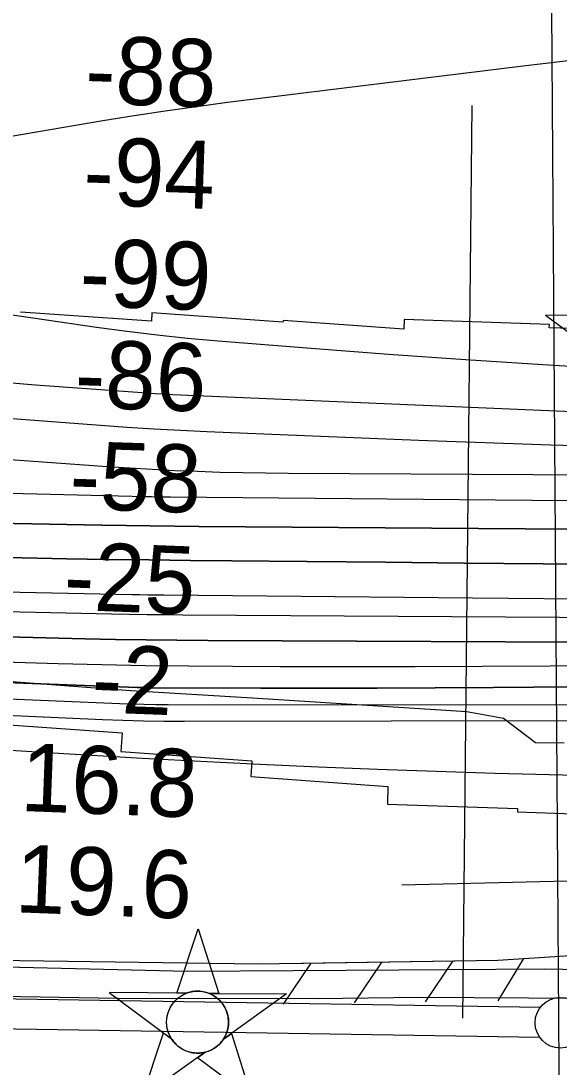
# Model space of a CAD drawing. Extents: x 3508733 to 3546731, y 546897 to 572481.
# Drawn here: x 3533417 to 3533948, y 561954 to 562985 of the extents above; entities that cross this region are included whole.
import ezdxf

# ---------------------------------------------------------------- set-up
doc = ezdxf.new("R2010")
doc.units = 0
for name, color, linetype in [('V-CHAN-NAID', 7, 'Continuous'), ('V-FLOD-BASE', 7, 'Continuous'), ('V-GRID-MAJR', 7, 'Continuous'), ('V-LEVE-TOET', 7, 'Continuous'), ('V-RIVR-EDGE', 7, 'Continuous'), ('V-RIVR-RANG', 7, 'Continuous'), ('V-RRAP-FSHR', 7, 'Continuous'), ('V-RRAP-RVMT', 7, 'Continuous'), ('V-SURV-LINE', 7, 'Continuous'), ('V-TOPO-DPTH', 7, 'Continuous'), ('V-TOPO-MAJR', 7, 'Continuous'), ('V-TOPO-MINR', 7, 'Continuous'), ('V-TOPO-WATR', 7, 'Continuous')]:
    doc.layers.add(name, color=color, linetype=linetype)

msp = doc.modelspace()

# ---------------------------------------------------------------- linework, layer by layer
at = {"layer": 'V-CHAN-NAID'}
msp.add_lwpolyline([(3534011.036, 562694.7280000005), (3533934.545, 562695.2700000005), (3533996.11, 562649.8710000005)], dxfattribs=at)
for points in [[(3533580.255, 562026.7770000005), (3533570.668, 562026.8450000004), (3533591.794, 562090.3290000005), (3533612.018, 562026.5520000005), (3533602.431, 562026.6200000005), (3533600.8540000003, 562027.1980000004), (3533598.759, 562027.8180000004), (3533596.719, 562028.2690000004), (3533594.683, 562028.5770000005), (3533593.5160000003, 562028.6910000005), (3533591.982, 562028.7720000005), (3533590.2600000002, 562028.7700000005), (3533588.89, 562028.7000000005), (3533586.984, 562028.4990000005), (3533585.6180000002, 562028.2800000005), (3533583.8340000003, 562027.8960000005), (3533582.304, 562027.4760000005), (3533581.272, 562027.1450000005)], [(3533580.255, 562026.7770000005), (3533503.764, 562027.3190000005), (3533565.329, 561981.9200000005), (3533564.216, 561983.8290000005), (3533563.406, 561985.4570000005), (3533562.5810000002, 561987.4250000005), (3533561.8850000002, 561989.4790000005), (3533561.52, 561990.8020000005), (3533561.159, 561992.4280000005), (3533560.915, 561993.8730000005), (3533560.727, 561995.4710000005), (3533560.6180000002, 561997.2070000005), (3533560.606, 561998.7880000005), (3533560.713, 562000.8620000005), (3533560.896, 562002.4800000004), (3533561.288, 562004.6830000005), (3533561.769, 562006.6060000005), (3533562.372, 562008.4930000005), (3533563.0270000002, 562010.1720000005), (3533563.754, 562011.7600000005), (3533564.568, 562013.2950000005), (3533565.629, 562015.0320000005), (3533566.66, 562016.5020000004), (3533567.66, 562017.7710000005), (3533568.662, 562018.9170000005), (3533569.971, 562020.2540000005), (3533571.022, 562021.2190000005), (3533572.739, 562022.6160000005), (3533573.951, 562023.4860000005), (3533575.6380000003, 562024.5560000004), (3533577.369, 562025.5010000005), (3533578.815, 562026.1850000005)], [(3533602.431, 562026.6200000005), (3533678.923, 562026.0770000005), (3533616.72, 561981.5550000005), (3533617.631, 561983.0440000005), (3533618.609, 561984.8910000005), (3533619.324, 561986.4760000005), (3533620.063, 561988.4310000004), (3533620.608, 561990.2160000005), (3533621.006, 561991.8550000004), (3533621.367, 561993.8650000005), (3533621.5530000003, 561995.4380000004), (3533621.677, 561997.6440000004), (3533621.647, 561999.7060000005), (3533621.4590000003, 562001.9260000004), (3533621.193, 562003.6840000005), (3533620.702, 562005.9160000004), (3533620.062, 562008.0560000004), (3533619.312, 562010.0380000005), (3533618.664, 562011.4810000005), (3533617.657, 562013.3970000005), (3533616.595, 562015.1190000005), (3533615.381, 562016.8210000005), (3533614.12, 562018.3600000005), (3533612.848, 562019.7260000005), (3533611.216, 562021.2580000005), (3533609.473, 562022.6700000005), (3533607.79, 562023.8470000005), (3533605.903, 562024.9790000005), (3533604.431, 562025.7400000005)], [(3533598.6890000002, 561968.6490000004), (3533536.486, 561924.1270000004), (3533557.612, 561987.6100000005), (3533565.329, 561981.9200000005), (3533565.964, 561980.9560000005), (3533567.347, 561979.0970000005), (3533568.56, 561977.6810000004), (3533570.026, 561976.1780000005), (3533571.415, 561974.9270000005), (3533572.869, 561973.7710000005), (3533574.272, 561972.7840000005), (3533575.95, 561971.7480000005), (3533577.664, 561970.8370000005), (3533579.455, 561970.0260000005), (3533580.901, 561969.4700000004), (3533582.529, 561968.9410000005), (3533584.755, 561968.3770000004), (3533586.287, 561968.0900000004), (3533588.312, 561967.8330000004), (3533589.849, 561967.7290000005), (3533591.71, 561967.7070000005), (3533593.399, 561967.7850000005), (3533595.109, 561967.9610000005), (3533597.011, 561968.2720000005)], [(3533616.72, 561981.5550000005), (3533624.5160000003, 561987.1360000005), (3533644.74, 561923.3590000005), (3533590.892, 561963.0690000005), (3533598.6890000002, 561968.6490000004), (3533600.355, 561969.1250000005), (3533601.967, 561969.6850000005), (3533604.125, 561970.5990000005), (3533605.86, 561971.4830000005), (3533607.7260000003, 561972.5970000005), (3533609.465, 561973.8090000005), (3533611.017, 561975.0540000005), (3533612.304, 561976.2220000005), (3533613.688, 561977.6420000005), (3533614.892, 561979.0440000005), (3533616.011, 561980.5160000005)]]:
    msp.add_lwpolyline(points, close=True, dxfattribs=at)
msp.add_circle((3533591.140887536, 561998.2429179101), 30.540600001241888, dxfattribs=at)
at = {"layer": 'V-FLOD-BASE'}
msp.add_lwpolyline([(3532710.45, 562040.6140000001), (3532907.802, 562036.26), (3533054.048, 562032.424), (3533261.9560000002, 562026.198), (3533512.771, 562021.889), (3533708.99, 562021.66), (3533810.0500000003, 562022.983), (3533971.599, 562021.928), (3534038.021, 562025.367), (3534206.162, 562037.169), (3534387.257, 562051.78), (3534513.098, 562063.427), (3534724.1750000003, 562080.083), (3534928.168, 562093.284), (3534994.62, 562099.66), (3535003.965, 562094.278), (3535028.649, 562095.201), (3535215.617, 562109.752), (3535302.065, 562118.274), (3535302.119, 562118.276)], dxfattribs=at)
at = {"layer": 'V-GRID-MAJR'}
msp.add_spline([(3534014.4590000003, 552440.283), (3533972.165, 558498.1140000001), (3533929.85, 564559.029), (3533887.535, 570619.961), (3533887.514, 570623.028)], degree=3, dxfattribs=at)
at = {"layer": 'V-LEVE-TOET'}
msp.add_lwpolyline([(3533987.153, 562049.381), (3533933.115, 562050.518), (3533789.759, 562049.625), (3533581.186, 562048.218), (3533401.458, 562052.394), (3533209.399, 562057.283), (3532981.536, 562065.473), (3532882.865, 562068.237)], dxfattribs=at)
at = {"layer": 'V-RIVR-EDGE'}
for points in [[(3532765.0349795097, 562381.7165799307), (3533031.5308730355, 562361.8471599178), (3533180.975664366, 562347.0697867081), (3533359.8496406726, 562337.6225832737), (3533524.908766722, 562325.207906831), (3533640.1544467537, 562318.3193444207), (3533856.838378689, 562304.5763614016), (3533892.8414277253, 562297.8837432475)], [(3533892.8414277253, 562297.8837432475), (3533924.5991676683, 562273.7921501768), (3533952.8143468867, 562273.7223821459)]]:
    msp.add_lwpolyline(points, dxfattribs=at)
at = {"layer": 'V-RIVR-RANG'}
msp.add_line((3533853.0094000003, 562002.0078000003), (3533862.1718, 562901.9612), dxfattribs=at)
at = {"layer": 'V-RRAP-FSHR'}
for p, q in [((3533702.97, 562056.527), (3533675.5810000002, 562016.101)), ((3533772.961, 562057.605), (3533745.572, 562017.178)), ((3533842.953, 562058.682), (3533815.5640000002, 562018.256)), ((3533912.894, 562061.019), (3533887.532, 562019.291))]:
    msp.add_line(p, q, dxfattribs=at)
for points in [[(3529520.034, 562301.447), (3530005.394, 562231.903), (3530463.257, 562162.518), (3530652.171, 562124.718), (3530699.6720000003, 562125.279), (3530728.12, 562143.471), (3530785.0160000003, 562179.856), (3530835.732, 562162.042), (3530871.386, 562134.303), (3530902.911, 562112.428), (3531136.153, 562100.238), (3531507.827, 562104.773), (3531883.571, 562094.2660000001), (3532389.292, 562081.3420000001), (3532875.907, 562077.706), (3533344.932, 562059.987), (3533650.721, 562055.723), (3533887.397, 562059.366), (3534147.489, 562076.225), (3534367.532, 562084.97), (3534626.011, 562110.182), (3534901.968, 562131.955), (3535007.86, 562142.192), (3535007.918, 562141.077)], [(3533674.674, 562056.0920000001), (3533887.397, 562059.366), (3534147.489, 562076.225), (3534581.443, 562108.767), (3534869.211, 562129.4450000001)]]:
    msp.add_lwpolyline(points, dxfattribs=at)
at = {"layer": 'V-RRAP-RVMT'}
for p, q in [((3533545.5020000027, 562689.2260000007), (3533416.5310000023, 562698.3640000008)), ((3533546.1040000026, 562697.6810000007), (3533545.5020000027, 562689.2260000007)), ((3533675.4140000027, 562688.5220000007), (3533546.1040000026, 562697.6810000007)), ((3533675.5170000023, 562689.9250000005), (3533675.4140000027, 562688.5220000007)), ((3533794.5290000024, 562681.4400000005), (3533675.5170000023, 562689.9250000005)), ((3533794.8740000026, 562690.9940000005), (3533794.5290000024, 562681.4400000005)), ((3533938.3320000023, 562686.0500000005), (3533794.8740000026, 562690.9940000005)), ((3533938.2240000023, 562682.7920000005), (3533938.3320000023, 562686.0500000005)), ((3534048.0226856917, 562678.960506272), (3533938.2240000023, 562682.7920000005)), ((3533400.4620000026, 562291.6900000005), (3533516.7260000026, 562283.4420000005)), ((3533516.7260000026, 562283.4420000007), (3533515.3570000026, 562265.1490000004)), ((3533515.357000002, 562265.1490000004), (3533644.7080000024, 562255.9520000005)), ((3533644.7080000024, 562255.9520000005), (3533643.5760000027, 562240.2740000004)), ((3533643.5760000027, 562240.2740000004), (3533779.0020000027, 562230.6690000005)), ((3533779.0020000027, 562230.6690000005), (3533778.4650000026, 562213.2860000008)), ((3533778.465000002, 562213.2860000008), (3533906.9700000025, 562208.8700000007)), ((3533906.9700000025, 562208.8700000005), (3533906.8510000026, 562205.6080000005)), ((3533906.8510000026, 562205.6080000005), (3534050.3390000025, 562200.6910000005))]:
    msp.add_line(p, q, dxfattribs=at)
at = {"layer": 'V-SURV-LINE'}
for points in [[(3530824.194358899, 562062.348565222), (3533929.4197166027, 562012.9924822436)], [(3533928.932137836, 561982.996442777), (3530823.707853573, 562032.3525086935)]]:
    msp.add_lwpolyline(points, dxfattribs=at)
msp.add_circle((3533949.1493600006, 561997.6767499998), 25, dxfattribs=at)
at = {"layer": 'V-TOPO-DPTH'}
for points in [[(3534328.0375129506, 562481.7770811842), (3533592.422935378, 562487.0036495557), (3533568.4560888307, 562487.2159632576), (3533544.4899679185, 562487.4843080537), (3533520.5249354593, 562487.8366994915), (3533496.560628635, 562488.2451220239), (3532943.5662781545, 562498.6397615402), (3532841.1358557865, 562500.9103593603)], [(3534328.0375129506, 562481.7770811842), (3533592.422935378, 562487.0036495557), (3533568.4560888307, 562487.2159632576), (3533544.4899679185, 562487.4843080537), (3533520.5249354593, 562487.8366994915), (3533496.560628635, 562488.2451220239), (3532943.5662781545, 562498.6397615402), (3532841.1358557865, 562500.9103593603)], [(3534009.8289911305, 562449.4472404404), (3533932.0733817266, 562450.1613299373), (3533854.317800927, 562450.8785106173), (3533776.562263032, 562451.6003280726), (3533698.806753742, 562452.3252367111), (3533624.813914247, 562453.0172726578), (3533584.05548622, 562453.4466371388), (3533543.2979116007, 562453.9402080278), (3533502.5416170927, 562454.5300885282), (3533461.786175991, 562455.1841754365), (3533403.7106097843, 562456.1848703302), (3533333.924918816, 562457.6275768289), (3533264.1484177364, 562459.3904038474), (3533194.3857014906, 562461.6334116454), (3533124.6321751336, 562464.1965399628), (3532367.9647438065, 562494.6083909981)], [(3532367.9647438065, 562494.6083909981), (3533124.6321751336, 562464.1965399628), (3533194.3857014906, 562461.6334116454), (3533264.1484177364, 562459.3904038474), (3533333.924918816, 562457.6275768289), (3533403.7106097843, 562456.1848703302), (3533461.786175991, 562455.1841754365), (3533502.5416170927, 562454.5300885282), (3533543.2979116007, 562453.9402080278), (3533584.05548622, 562453.4466371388), (3533624.813914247, 562453.0172726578), (3533698.806753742, 562452.3252367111), (3533776.562263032, 562451.6003280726), (3533854.317800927, 562450.8785106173), (3533932.0733817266, 562450.1613299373), (3534009.8289911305, 562449.4472404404)], [(3532827.841545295, 562434.5562286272), (3532928.577339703, 562432.2108043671), (3533526.362860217, 562419.9304948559), (3533534.2225623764, 562419.7820168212), (3533542.0825247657, 562419.6508448), (3533549.9428774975, 562419.5456317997), (3533557.8034904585, 562419.4577248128), (3533862.278117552, 562416.5555530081), (3534004.12328421, 562415.2455137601)], [(3532827.841545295, 562434.5562286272), (3532928.577339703, 562432.2108043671), (3533526.362860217, 562419.9304948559), (3533534.2225623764, 562419.7820168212), (3533542.0825247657, 562419.6508448), (3533549.9428774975, 562419.5456317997), (3533557.8034904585, 562419.4577248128), (3533862.278117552, 562416.5555530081), (3534004.12328421, 562415.2455137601)], [(3534674.874702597, 562334.7051032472), (3533882.987928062, 562328.2196209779), (3533825.6283864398, 562327.8455993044), (3533768.268509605, 562327.5992354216), (3533710.90812995, 562327.5443582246), (3533653.5474150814, 562327.6171388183), (3533546.255968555, 562327.9323608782), (3533542.541117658, 562327.962606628), (3533538.8267894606, 562328.0186197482), (3533535.113245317, 562328.1132839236), (3533531.400223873, 562328.2337154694), (3533436.317086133, 562331.8131198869), (3533385.068187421, 562333.8596397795), (3533333.8263543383, 562336.0622264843), (3533282.595119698, 562338.4989134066), (3533231.370950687, 562341.091667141), (3532367.406045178, 562386.8009990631)], [(3534674.874702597, 562334.7051032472), (3533882.987928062, 562328.2196209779), (3533825.6283864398, 562327.8455993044), (3533768.268509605, 562327.5992354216), (3533710.90812995, 562327.5443582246), (3533653.5474150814, 562327.6171388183), (3533546.255968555, 562327.9323608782), (3533542.541117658, 562327.962606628), (3533538.8267894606, 562328.0186197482), (3533535.113245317, 562328.1132839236), (3533531.400223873, 562328.2337154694), (3533436.317086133, 562331.8131198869), (3533385.068187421, 562333.8596397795), (3533333.8263543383, 562336.0622264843), (3533282.595119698, 562338.4989134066), (3533231.370950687, 562341.091667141), (3532367.406045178, 562386.8009990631)], [(3534041.5508859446, 562372.4465537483), (3533601.1149682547, 562374.4540545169), (3533570.802779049, 562374.6864568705), (3533540.492464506, 562375.0444925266), (3533510.1849619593, 562375.5909781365), (3533479.8793340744, 562376.2630970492), (3533132.402644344, 562385.0503072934), (3532997.2561912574, 562388.9353019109), (3532862.1326553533, 562393.4427489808)], [(3532862.1326553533, 562393.4427489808), (3532997.2561912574, 562388.9353019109), (3533132.402644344, 562385.0503072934), (3533479.8793340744, 562376.2630970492), (3533510.1849619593, 562375.5909781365), (3533540.492464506, 562375.0444925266), (3533570.802779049, 562374.6864568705), (3533601.1149682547, 562374.4540545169), (3534041.5508859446, 562372.4465537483)], [(3532751.7445428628, 562330.2057441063), (3533497.2336551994, 562296.7619895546), (3533517.4447677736, 562295.9958270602), (3533537.6599405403, 562295.4167831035), (3533557.881203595, 562295.1184169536), (3533578.106526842, 562295.0071693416), (3534598.420280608, 562296.4776848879)]]:
    msp.add_lwpolyline(points, dxfattribs=at)
at = {"layer": 'V-TOPO-MAJR'}
msp.add_lwpolyline([(3532845.0481750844, 562534.212838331), (3532947.709127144, 562531.0870076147), (3533526.6341207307, 562516.8358718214), (3533536.077092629, 562516.6253050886), (3533545.520557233, 562516.4439069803), (3533554.9647608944, 562516.3062618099), (3533564.4094572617, 562516.1977852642), (3534027.842054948, 562511.9487101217)], dxfattribs=at)
at = {"layer": 'V-TOPO-MINR'}
for points in [[(3534017.186804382, 562953.427631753), (3533942.991704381, 562944.3611781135), (3533912.379515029, 562940.6532825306), (3533853.483632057, 562933.495508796), (3533794.5916146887, 562926.3061751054), (3533735.7053957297, 562919.0695014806), (3533676.823042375, 562911.8012678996), (3533620.7894629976, 562904.8618105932), (3533589.9568338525, 562900.834563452), (3533559.1642353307, 562896.5339990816), (3533528.431682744, 562891.823458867), (3533497.73916078, 562886.8396014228), (3533353.0471860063, 562862.3537700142)], [(3533172.389702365, 562730.1351540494), (3533491.4672950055, 562683.5575966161), (3533521.346159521, 562679.4958921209), (3533551.2692893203, 562675.8272104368), (3533581.258817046, 562672.7480629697), (3533611.292610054, 562670.0619383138), (3533703.3504827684, 562662.7409952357), (3533779.464738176, 562656.9600245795), (3533855.6033871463, 562651.5398038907), (3533931.778626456, 562646.6607081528), (3534007.978259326, 562642.1423623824)], [(3532645.3105241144, 562709.4598774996), (3533195.5964000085, 562648.4505202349), (3533254.416922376, 562642.2551991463), (3533313.2772000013, 562636.4900439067), (3533372.1971105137, 562631.3701374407), (3533431.1567762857, 562626.6803968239), (3533531.9282530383, 562619.2202253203), (3533540.534351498, 562618.623448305), (3533549.1435777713, 562618.0802122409), (3533557.7574957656, 562617.6172876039), (3533566.374541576, 562617.2079039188), (3534301.259970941, 562585.7283853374)], [(3532846.3197089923, 562637.1328926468), (3532972.7385672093, 562626.6551017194), (3533099.2012615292, 562616.6874460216), (3533495.4961945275, 562586.6587624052), (3533521.696076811, 562584.8127254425), (3533547.9066898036, 562583.1514563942), (3533574.13339886, 562581.7673392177), (3533600.370838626, 562580.5679899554), (3533809.162846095, 562572.1294540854), (3533939.8198957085, 562567.5094736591), (3534070.497681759, 562563.7693188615)], [(3532861.6699301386, 562592.5939456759), (3532992.776507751, 562583.0289614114), (3533123.885609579, 562573.4984825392), (3533501.8397734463, 562546.0995364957), (3533524.157265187, 562544.6081061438), (3533546.4837590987, 562543.2845423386), (3533568.823756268, 562542.212778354), (3533591.1727556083, 562541.3088809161), (3533613.530491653, 562540.6298725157), (3533635.890871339, 562540.0827763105), (3533658.2552164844, 562539.7335483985), (3533680.6222052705, 562539.5162326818), (3534649.102963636, 562534.3915936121)], [(3532841.1358557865, 562500.9103593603), (3532943.5662781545, 562498.6397615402), (3533496.560628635, 562488.2451220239), (3533520.5249354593, 562487.8366994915), (3533544.4899679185, 562487.4843080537), (3533568.4560888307, 562487.2159632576), (3533592.422935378, 562487.0036495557), (3534328.0375129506, 562481.7770811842)], [(3532367.9647438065, 562494.6083909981), (3533124.6321751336, 562464.1965399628), (3533194.3857014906, 562461.6334116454), (3533264.1484177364, 562459.3904038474), (3533333.924918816, 562457.6275768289), (3533403.7106097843, 562456.1848703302), (3533461.786175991, 562455.1841754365), (3533502.5416170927, 562454.5300885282), (3533543.2979116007, 562453.9402080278), (3533584.05548622, 562453.4466371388), (3533624.813914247, 562453.0172726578), (3533698.806753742, 562452.3252367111), (3533776.562263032, 562451.6003280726), (3533854.317800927, 562450.8785106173), (3533932.0733817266, 562450.1613299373), (3534009.8289911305, 562449.4472404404)], [(3533792.69, 562133.7000000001), (3535332.95555223, 562170.7301294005), (3535423.6286592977, 562173.7056624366), (3535514.245328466, 562177.7399177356), (3535604.7773407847, 562183.36225643), (3535695.252915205, 562190.0433173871), (3535863.101832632, 562203.9185593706), (3535869.5970063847, 562204.5571959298), (3535876.0741093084, 562205.3296531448), (3535882.5241059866, 562206.3028413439), (3535888.956031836, 562207.4098501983), (3537178.662136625, 562450.0655293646)], [(3532827.841545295, 562434.5562286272), (3532928.577339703, 562432.2108043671), (3533526.362860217, 562419.9304948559), (3533534.2225623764, 562419.7820168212), (3533542.0825247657, 562419.6508448), (3533549.9428774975, 562419.5456317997), (3533557.8034904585, 562419.4577248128), (3533862.278117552, 562416.5555530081), (3534004.12328421, 562415.2455137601)], [(3532574.323304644, 562421.0864822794), (3533506.174948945, 562400.882749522), (3533523.7828552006, 562400.5417585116), (3533541.3915202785, 562400.2551095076), (3533559.0013235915, 562400.0499735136), (3533576.611885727, 562399.8991795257), (3534691.1991970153, 562392.9351675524)], [(3532352.556235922, 562403.715808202), (3533151.729977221, 562363.4382502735), (3533216.34463667, 562360.3862551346), (3533280.9701406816, 562357.606380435), (3533345.611911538, 562355.2346863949), (3533410.264526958, 562353.1351127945), (3533453.5929260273, 562351.8649846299), (3533496.592221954, 562350.7757467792), (3533539.5951785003, 562349.91469213), (3533582.603625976, 562349.3959122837), (3533625.615734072, 562349.105315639), (3533672.687215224, 562348.9746179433), (3533739.2376779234, 562348.8758664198), (3533805.7879648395, 562348.8918217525), (3533872.3379880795, 562349.0798373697), (3533938.887835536, 562349.3825598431), (3534675.750866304, 562353.6869871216)], [(3532862.1326553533, 562393.4427489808), (3532997.2561912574, 562388.9353019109), (3533132.402644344, 562385.0503072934), (3533479.8793340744, 562376.2630970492), (3533510.1849619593, 562375.5909781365), (3533540.492464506, 562375.0444925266), (3533570.802779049, 562374.6864568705), (3533601.1149682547, 562374.4540545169), (3534041.5508859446, 562372.4465537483)], [(3532791.986949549, 562345.0991952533), (3532941.1889506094, 562337.3934655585), (3533090.4253471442, 562330.3853745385), (3533239.684673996, 562323.8423759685), (3533514.317187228, 562312.4466246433), (3533526.278999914, 562312.0236682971), (3533538.242870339, 562311.6984507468), (3533550.209827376, 562311.5198413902), (3533562.1788421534, 562311.438970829), (3533984.039864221, 562311.1732147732)], [(3532751.7445428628, 562330.2057441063), (3533497.2336551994, 562296.7619895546), (3533517.4447677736, 562295.9958270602), (3533537.6599405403, 562295.4167831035), (3533557.881203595, 562295.1184169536), (3533578.106526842, 562295.0071693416), (3534598.420280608, 562296.4776848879)], [(3532505.1625289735, 562322.6705921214), (3533459.3165945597, 562263.0645580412), (3533497.833992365, 562260.7374688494), (3533536.3572359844, 562258.5154688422), (3533574.8892483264, 562256.4511026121), (3533613.427106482, 562254.4918255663), (3533652.4306559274, 562252.5888615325), (3533710.4819927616, 562249.9516223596), (3533768.5430878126, 562247.573956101), (3533826.6188201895, 562245.5856492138), (3533884.704310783, 562243.8569152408), (3534018.348664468, 562240.327821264)]]:
    msp.add_lwpolyline(points, dxfattribs=at)
at = {"layer": 'V-TOPO-WATR'}
msp.add_lwpolyline([(3532367.406045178, 562386.8009990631), (3533231.370950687, 562341.091667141), (3533282.595119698, 562338.4989134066), (3533333.8263543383, 562336.0622264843), (3533385.068187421, 562333.8596397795), (3533436.317086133, 562331.8131198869), (3533531.400223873, 562328.2337154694), (3533535.113245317, 562328.1132839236), (3533538.8267894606, 562328.0186197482), (3533542.541117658, 562327.962606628), (3533546.255968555, 562327.9323608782), (3533653.5474150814, 562327.6171388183), (3533710.90812995, 562327.5443582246), (3533768.268509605, 562327.5992354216), (3533825.6283864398, 562327.8455993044), (3533882.987928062, 562328.2196209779), (3534674.874702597, 562334.7051032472)], dxfattribs=at)

# ---------------------------------------------------------------- texts
at = {"layer": 'V-RIVR-RANG'}
for s, height, rotation, p in [('-88', 67.00000000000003, 358.1053611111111, (3533479.4179315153, 562904.1607737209)), ('-94', 67.00000000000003, 358.1053611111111, (3533477.7103787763, 562804.1637267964)), ('-99', 67.00000000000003, 358.1053611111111, (3533474.156378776, 562704.2267267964)), ('-86', 67.00000000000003, 358.1053611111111, (3533469.285202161, 562604.3333317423)), ('-58', 67.00000000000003, 358.1053611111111, (3533464.1503902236, 562504.4486576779)), ('-25', 67, 357.81832571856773, (3533458.334392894, 562405.0033903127)), ('-2', 67, 357.81832571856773, (3533485.8848152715, 562303.8814801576)), ('16.8', 67, 357.81832571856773, (3533415.6439689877, 562206.4850078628)), ('19.6', 67, 357.81832571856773, (3533410.245850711, 562106.6192991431))]:
    msp.add_text(s, height=height, rotation=rotation, dxfattribs=at).set_placement(p)

doc.saveas('drawing.dxf')
